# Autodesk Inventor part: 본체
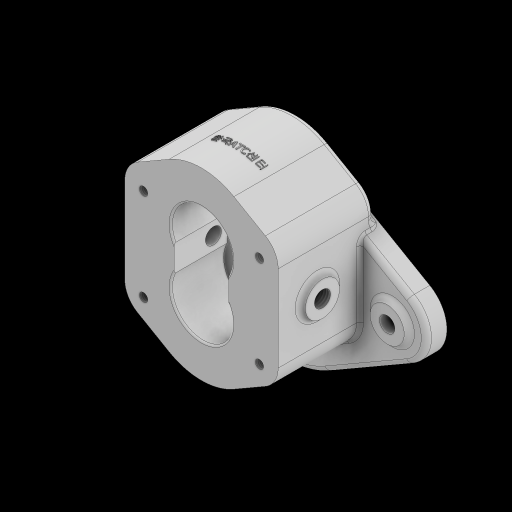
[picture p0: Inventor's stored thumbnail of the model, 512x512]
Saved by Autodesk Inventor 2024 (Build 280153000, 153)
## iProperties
Created: 2025-11
Part Number: 본체
Material: 일반
Document SubType Name: Modeling
Designer: EDU03
Density: 1 g/cm^3
Appearance: 기본값
Author: EDU03
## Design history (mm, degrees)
sketch "스케치1" dims "d0" = 104, "d2" = 40
  geometry: L1 (0, 0)-(0, 84.803); L2 (-74, 17.321)-(-26, 45.033); L3 (74, 17.321)-(26, 45.033); L4 (0, 0)-(28.765, 0); L5 (74, -17.321)-(26, -45.033); L6 (-74, -17.321)-(-26, -45.033); C1 r 20 at (64, 0); 8 further points
  constraints: 12 end point, 7 symmetric about line, 1 centre point, 1 coincident, 1 horizontal, 1 horizontal alignment, 1 vertical, 9 other
  dimensions: "d1" = 128 diameter of point (-64, 0) L1
extrude "돌출1" new body sketch "스케치1" distance "d3" = 12; taper "d4" = 0 deg
sketch "스케치2"
  geometry: L1 (-26, 45.033)-(-74, 17.321) reference; L2 (-74, -17.321)-(-26, -45.033) reference; L3 (26, -45.033)-(74, -17.321) reference; L4 (74, 17.321)-(26, 45.033) reference; C1 r 10 at (-64, 0); C2 r 10 at (64, 0); A1 r 20 centre (-64, 0) between (-74, 17.321) and (-74, -17.321) reference; A2 r 52 centre (0, 0) between (-26, -45.033) and (26, -45.033) reference; A3 r 20 centre (64, 0) between (74, -17.321) and (74, 17.321) reference; A4 r 52 centre (0, 0) between (26, 45.033) and (-26, 45.033) reference; 1 further point
  constraints: 2 centre point, 2 coincident
  dimensions: "d5" = 20 diameter of C1; "d6" = 20 diameter of C2
extrude "돌출2" join sketch "스케치2" distance "d7" = 3; taper "d8" = 0 deg
sketch "스케치3"
  geometry: C1 r 10 at (0, 0) reference; C2 r 10 at (128, 0) reference; 3 further points
  constraints: 2 coincident
hole "구멍1" sketch "스케치3" at (0, 0), (128, 0) diameter "d9" = 9; stored, may be unused: countersink angle "d13" = 90 deg, drill point angle "d15" = 118 deg; dims "d10" = 6, "d11" = 4, "d12" = 2, "d14" = 8
sketch "스케치4"
  geometry: C1 r 25 at (0, 0); 1 further point
  constraints: 1 centre point, 1 coincident
  dimensions: "d16" = 50 diameter of C1
extrude "돌출3" join sketch "스케치4" distance "d17" = 4; taper "d18" = 0 deg
fillet "모깎기1" dims "d19" = 3
chamfer "모따기1" distance "d20" = 1; stored, may be unused: second distance "d21" = 2, angle "d22" = 45 deg
sketch "스케치5"
  geometry: L1 (0, 0)-(0, 16); L2 (0, 16)-(0, 32); L3 (-34, 98.421)-(-34, -70.713); L4 (0, 0)-(15.008, 0); L5 (-60.9, 43)-(46.18, 43); L6 (0, 16)-(11.834, 16); L7 (14.497, 67.509)-(45, 49.898); L8 (34, 43)-(34, -11); L9 (-45, -22.719)-(-45, 54.719); L10 (45, -22.719)-(45, 49.898); L11 (14.497, -35.509)-(45, -17.898); L12 (-14.497, 67.509)-(-45, 49.898); L13 (-14.497, -35.509)-(-45, -17.898); C1 r 38 at (0, 32); C2 r 38 at (0, 0); C3 r 2.163 at (-38.837, -22.891); 4 further points
  constraints: 26 end point, 10 symmetric about line, 4 vertical, 3 centre point, 3 horizontal, 2 coincident, 2 parallel, 1 point on line, 1 tangent
  dimensions: "d23" = 16 distance of L1.start L1.end; "d24" = 16 distance of L1.end L2.end; "d25" = 76 diameter of C1; "d26" = 76 diameter of C2; "d27" = 34 distance from line of L1.start L3; "d34" = 54 distance of L8.end L8.start; "d68" = 45 distance between parallel lines of L1 L9; "d69" = 45 distance between parallel lines of L1 L10; "d70" = 30 deg angle of L6 L7
node "작업 평면1"
sketch "스케치6"
  geometry: L1 (-14.497, 67.509)-(-45, 49.898) reference; L2 (-45, -22.719)-(-45, 49.898) reference; L3 (-14.497, -35.509)-(-45, -17.898) reference; L4 (14.497, -35.509)-(45, -17.898) reference; L5 (45, -22.719)-(45, 54.719) reference; L6 (14.497, 67.509)-(45, 49.898) reference; C1 r 38 at (0, 32) reference; C2 r 38 at (0, 0) reference
node "작업 평면3"
node "작업 평면4"
sketch "스케치8"
  geometry: L1 (-39.652, 56.895)-(-14.318, 67.199) reference; L2 (39.652, -24.895)-(14.318, -35.199) reference; L3 (0, 0)-(0, 32); L4 (-16, 0)-(-16, 32); L5 (16, 0)-(16, 32); C1 r 18 at (0, 32); C2 r 18 at (0, 0); A1 r 2.458 centre (34, -11) between (36.446, -10.755) and (35.839, -12.631) reference; A2 r 2.458 centre (34, 43) between (35.839, 44.631) and (36.446, 42.755) reference; A3 r 2.458 centre (-34, 43) between (-36.446, 42.755) and (-35.839, 44.631) reference; A4 r 15 centre (34, 43) between (28.617, 57.001) and (37.838, 28.499) reference; A5 r 38 centre (0, 32) between (-14.318, 67.199) and (-28.617, 57.001) reference; A6 r 15 centre (-34, 43) between (-28.617, 57.001) and (-39.652, 56.895) reference; A7 r 38 centre (0, 0) between (36.446, -10.755) and (37.838, 3.501) reference; A8 r 15 centre (34, -11) between (37.838, 3.501) and (28.617, -25.001) reference; A9 r 38 centre (0, 32) between (-34.467, 16) and (34.467, 16) reference; A10 r 38 centre (0, 0) between (34.467, 16) and (-34.467, 16) reference; A11 r 15 centre (34, -11) between (28.617, -25.001) and (39.652, -24.895) reference; A12 r 38 centre (0, 0) between (14.318, -35.199) and (28.617, -25.001) reference; A13 r 38 centre (0, 32) between (-36.446, 42.755) and (-37.838, 28.499) reference; A14 r 15 centre (-34, 43) between (-37.838, 28.499) and (-28.617, 57.001) reference; A15 r 38 centre (0, 32) between (-28.617, 57.001) and (-35.839, 44.631) reference; A16 r 38 centre (0, 32) between (35.839, 44.631) and (28.617, 57.001) reference; A17 r 38 centre (0, 32) between (37.838, 28.499) and (36.446, 42.755) reference; A18 r 38 centre (0, 0) between (28.617, -25.001) and (35.839, -12.631) reference; 5 further points
  constraints: 6 end point, 2 centre point, 2 coincident, 2 parallel, 1 vertical
  dimensions: "d42" = 36 diameter of C1; "d43" = 36 diameter of C2; "d44" = 16 distance between parallel lines of L3 L4; "d45" = 16 distance between parallel lines of L3 L5
extrude "돌출5" cut sketch "스케치8" distance "d46" = 31; taper "d47" = 0 deg
node "작업 평면8"
sketch "스케치10"
  geometry: L1 (16, 23.754)-(16, 8.246) reference; L2 (-16, 8.246)-(-16, 23.754) reference; C1 r 11.5 at (0, 32); C2 r 11.5 at (0, 0); A1 r 18 centre (0, 0) between (17.937, -1.5) and (16, 8.246) reference; A2 r 18 centre (0, 32) between (-17.937, 33.5) and (-16, 23.754) reference; A3 r 38 centre (0, 0) between (17.937, 33.5) and (-17.937, 33.5) reference; A4 r 18 centre (0, 0) between (-16, 8.246) and (-17.937, -1.5) reference; A5 r 38 centre (0, 32) between (-17.937, -1.5) and (17.937, -1.5) reference; A6 r 18 centre (0, 32) between (16, 23.754) and (17.937, 33.5) reference; 1 further point
  constraints: 2 centre point, 2 coincident
  dimensions: "d48" = 23 diameter of C1; "d49" = 23 diameter of C2
extrude "돌출6" cut sketch "스케치10" distance "d50" = 46; taper "d51" = 0 deg
sketch "스케치12"
  geometry: C1 r 15 at (0, 0); 1 further point
  constraints: 1 centre point, 1 coincident
  dimensions: "d55" = 30 diameter of C1
extrude "돌출8" cut sketch "스케치12" distance "d56" = 7.3; taper "d57" = 0 deg
fillet "모깎기3" dims "d61" = 0.3
chamfer "모따기3" distance "d62" = 0.35; stored, may be unused: second distance "d63" = 0.7, angle "d64" = 45 deg
node "작업 평면7"
sketch "스케치14"
  geometry: L1 (-14.497, 67.509)-(-45, 49.898) reference; L2 (-45, -22.719)-(-45, 54.719) reference; L3 (-14.497, -35.509)-(-45, -17.898) reference; L4 (14.497, -35.509)-(45, -17.898) reference; L5 (45, -22.719)-(45, 49.898) reference; L6 (14.497, 67.509)-(45, 49.898) reference; C1 r 38 at (0, 32) reference; C2 r 38 at (0, 0) reference; 5 further points
extrude "돌출9" join sketch "스케치14" distance "d71" = 56; taper "d72" = 0 deg
sketch "스케치15"
  geometry: L1 (45, -17.898)-(45, 49.898) reference; L2 (45, 49.898)-(19, 64.909) reference; L3 (-19, 64.909)-(-45, 49.898) reference; L4 (-45, 49.898)-(-45, -17.898) reference; L5 (-45, -17.898)-(-19, -32.909) reference; L6 (19, -32.909)-(45, -17.898) reference; A1 r 38 centre (0, 32) between (19, 64.909) and (-19, 64.909) reference; A2 r 38 centre (0, 0) between (-19, -32.909) and (19, -32.909) reference; 5 further points
  constraints: 2 vertical alignment
  dimensions: "d119" = 68 distance of point (-34, 41.238) point (34, 41.238); "d120" = 34 horizontal distance of A1.centre point (34, 41.238); "d121" = 54 distance of point (34, -12.762) point (34, 41.238); "d122" = 54 distance of point (-34, 41.238) point (-34, -12.762)
hole "구멍3" sketch "스케치15" at (-34, -12.762), (-34, 41.238), (34, 41.238), (34, -12.762) diameter "d74" = 4.917; stored, may be unused: countersink angle "d78" = 90 deg, drill point angle "d80" = 118 deg; dims "d75" = 12, "d76" = 4, "d77" = 2, "d79" = 14
node "작업 평면9"
sketch "스케치16"
  geometry: L1 (0, 0)-(0, 32); L2 (16, 0)-(16, 32); L3 (-16, 0)-(-16, 32); C1 r 18 at (0, 0); C2 r 18 at (0, 32); 5 further points
  constraints: 6 end point, 2 centre point, 2 coincident, 2 parallel, 1 vertical
  dimensions: "d81" = 36 diameter of C1; "d82" = 32 distance of L1.start L1.end; "d83" = 36 diameter of C2; "d84" = 16 distance between parallel lines of L1 L2; "d85" = 16 distance between parallel lines of L1 L3
extrude "돌출10" cut sketch "스케치16" distance "d86" = 31; taper "d87" = 0 deg
node "작업 평면10"
sketch "스케치17"
  geometry: L1 (-16, 8.246)-(-16, 23.754) reference; L2 (16, 23.754)-(16, 8.246) reference; L3 (45, -17.898)-(45, 49.898) reference; L4 (45, 49.898)-(19, 64.909) reference; L5 (-19, 64.909)-(-45, 49.898) reference; L6 (-45, 49.898)-(-45, -17.898) reference; L7 (-45, -17.898)-(-19, -32.909) reference; L8 (19, -32.909)-(45, -17.898) reference; C1 r 11.5 at (0, 0); C2 r 2.458 at (-34, -12.762) reference; C3 r 11.5 at (0, 32); A1 r 18 centre (0, 32) between (16, 23.754) and (-16, 23.754) reference; A2 r 18 centre (0, 0) between (-16, 8.246) and (16, 8.246) reference; A3 r 38 centre (0, 32) between (19, 64.909) and (-19, 64.909) reference; A4 r 38 centre (0, 0) between (-19, -32.909) and (19, -32.909) reference; 1 further point
  constraints: 2 centre point, 1 coincident
  dimensions: "d88" = 23 diameter of C1; "d89" = 23 diameter of C3
extrude "돌출11" cut sketch "스케치17" distance "d90" = 24; taper "d91" = 0 deg
node "작업 평면11"
sketch "스케치18"
  geometry: C1 r 10.5 at (0, 0); 1 further point
  constraints: 1 centre point, 1 coincident
  dimensions: "d92" = 21 diameter of C1
extrude "돌출12" cut sketch "스케치18" extent not by distance; stored distance "d93" = 0; taper "d94" = 0 deg
fillet "모깎기5" dims "d97" = 15
node "작업 평면12"
sketch "스케치21"
  geometry: L1 (-51, -10.31)-(-51, -25.817) reference; L2 (-51, -18.064)-(-28, -18.064); C1 r 10 at (-28, -18.064); 1 further point
  constraints: 2 end point, 1 centre point, 1 coincident, 1 horizontal, 1 midpoint
  dimensions: "d99" = 23 distance of L2.start L2.end; "d100" = 20 diameter of C1
extrude "돌출13" join sketch "스케치21" stored distance "d101" = 10; taper "d102" = 0 deg
sketch "스케치22"
  geometry: L1 (-23, -25.238)-(-23, 25.238) reference; C1 r 10 at (0, 0) reference; 2 further points
  constraints: 1 coincident
  dimensions: "d114" = 23 distance from line of point (0, 0) L1 (derived)
hole "구멍4" sketch "스케치22" at (0, 0) diameter "d103" = 9.3762; stored, may be unused: countersink angle "d107" = 90 deg, drill point angle "d109" = 118 deg; dims "d104" = 22, "d105" = 4, "d106" = 2, "d108" = 14
feature "스레드1" dims "d110" = 5, "d111" = 0
fillet "모깎기6" dims "d112" = 3
fillet "모깎기7" dims "d113" = 1
node "작업축1"
node "작업 평면14"
sketch "스케치23"
  geometry: 2 further points
  constraints: 1 other
feature "엠보싱1" sketch "스케치23" dims "d115" = 0.5, "d116" = 0
fillet "모깎기8" dims "d117" = 3
fillet "모깎기9" dims "d118" = 2
node "솔리드1"
mirror "미러1"
node "투영된 루프1"
node "투영된 루프3"
node "투영된 루프4"
node "투영된 루프5"
node "투영된 루프6"
feature "A9D066F2-1C7D-4E18-AEED-F7BC21143FA4" dims "d74" = 4.917, "d75" = 12, "d76" = 4, "d77" = 2, "d78" = 90 deg, "d79" = 14, "d80" = 118 deg
other parameters: "d30" = -64, "d98" = 3
